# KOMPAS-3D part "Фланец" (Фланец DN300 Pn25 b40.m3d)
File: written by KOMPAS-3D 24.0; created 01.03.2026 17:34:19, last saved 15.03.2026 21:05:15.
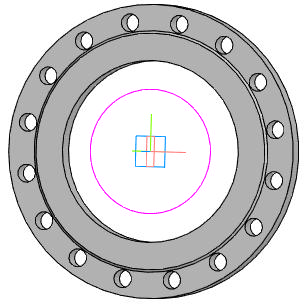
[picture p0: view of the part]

Document properties: Автор: R2D2; Полное имя файла: E:\Работа\Зайцев\GVWR2434M-2W-F-ОСТ Задвижка клиновая с выдвижным штоком DN.ru Ду50-300 Ру25\исходные материалы\DN300\Фланец DN300 Pn25 b40.m3d

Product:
- Part/product: Фланец
    Масса: 30.669442
    additional columns: Типовые

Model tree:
1. Эскиз:2
2. Элемент вращения:1
     Угол 1 = 360
3. Эскиз:3  (with: Грань.Элемент вращения:1)
4. Элемент выдавливания:2
     Расстояние 2 = 36
5. Массив по концентрической сетке:1  (with: Элемент выдавливания:2, Эскиз:3, Грань.Элемент вращения:1)  (16 pattern instances)
     Шаг 2 = 360
6. Эскиз:4  (with: Грань.Элемент вращения:1)
7. Элемент выдавливания:3
     Расстояние 2 = 4

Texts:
  Линейный размер с обрывом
